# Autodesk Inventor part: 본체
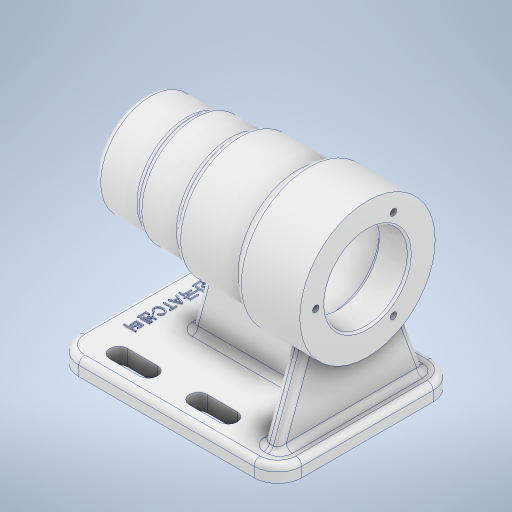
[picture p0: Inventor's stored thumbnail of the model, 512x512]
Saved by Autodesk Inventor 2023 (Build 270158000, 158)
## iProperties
Created: 2022-07
Part Number: 본체
Material: 알루미늄 6061
Document SubType Name: Modeling
Designer: owner
Density: 2.7 g/cm^3
Appearance: 알루미늄 - 평지
Mass: 695.124 g
Surface Area: 704.983 cm^2
Volume: 257.453 cm^3
Author: owner
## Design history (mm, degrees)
sketch "스케치1"
  geometry: L1 (44, -45)-(-44, -45); L2 (-56, -33)-(-56, 33); L3 (-44, 45)-(44, 45); L4 (56, 33)-(56, -33); L5 (56, -45)-(-56, 45); L6 (-56, -45)-(56, 45); A1 r 12 centre (44, -33) between (44, -45) and (56, -33); A2 r 12 centre (44, 33) between (56, 33) and (44, 45); A3 r 12 centre (-44, 33) between (-44, 45) and (-56, 33); A4 r 12 centre (-44, -33) between (-56, -33) and (-44, -45); 1 further point
  constraints: 12 end point, 8 point on circle, 8 point on line, 8 tangent, 4 centre point, 3 equal radius, 2 midpoint, 2 parallel, 1 horizontal, 1 perpendicular
  dimensions: "d0" = 112 distance of L5.end L6.end; "d1" = 90 distance of L6.start L5.end; "d2" = 12 radius of A1
extrude "돌출1" new body sketch "스케치1" distance "d3" = 8; taper "d4" = 0 deg
sketch "스케치2"
  geometry: L1 (-36, 33)-(-21, 33); L2 (-36, 28.5)-(-21, 28.5); L3 (-21, 37.5)-(-36, 37.5); L4 (4, 33)-(19, 33); L5 (4, 28.5)-(19, 28.5); L6 (19, 37.5)-(4, 37.5); L7 (56, -33)-(56, 33) reference; L8 (-56, 33)-(-56, -33) reference; L9 (-56, 33)-(-56, -33) reference; L10 (-56, 0)-(56, 0); L11 (-21, -37.5)-(-36, -37.5); L12 (-36, -28.5)-(-21, -28.5); L13 (19, -37.5)-(4, -37.5); L14 (4, -28.5)-(19, -28.5); A1 r 4.5 centre (-36, 33) between (-36, 37.5) and (-36, 28.5); A2 r 4.5 centre (-21, 33) between (-21, 28.5) and (-21, 37.5); A3 r 4.5 centre (4, 33) between (4, 37.5) and (4, 28.5); A4 r 4.5 centre (19, 33) between (19, 28.5) and (19, 37.5); A5 r 4.5 centre (-21, -33) between (-21, -37.5) and (-21, -28.5); A6 r 4.5 centre (-36, -33) between (-36, -28.5) and (-36, -37.5); A7 r 4.5 centre (4, -33) between (4, -28.5) and (4, -37.5); A8 r 4.5 centre (19, -33) between (19, -37.5) and (19, -28.5); 3 further points
  constraints: 26 end point, 16 point on circle, 12 symmetric about line, 8 centre point, 8 tangent, 4 midpoint, 2 horizontal, 2 parallel, 4 other
  dimensions: "d5" = 15 distance of L1.start L1.end; "d6" = 9 diameter of A2; "d7" = 15 distance of L4.start L4.end; "d8" = 9 diameter of A4; "d10" = 33 vertical distance of point (0, 0) point (-28.5, 33); "d11" = 33 vertical distance of point (0, 0) point (11.5, 33); "d12" = 25 distance of L4.start L1.end; "d13" = 20 distance from line of L8 L1.start
extrude "돌출2" cut sketch "스케치2" extent not by distance; stored distance "d14" = 0; taper "d15" = 0 deg
sketch "스케치3"
  geometry: L1 (-56, 70)-(56, 70); L2 (-44, 0)-(44, 0) reference; L3 (56, 70)-(56, 104); L4 (56, 104)-(24, 104); L5 (24, 104)-(24, 100); L6 (24, 100)-(-10, 100); L7 (-10, 100)-(-10, 97); L8 (-10, 97)-(-32, 97); L9 (-32, 97)-(-32, 95); L10 (-32, 95)-(-56, 95); L11 (-56, 95)-(-56, 70); L12 (56, 91)-(41, 91); L13 (41, 91)-(41, 91); L14 (38, 94)-(-10, 94); L15 (-13, 91)-(-13, 91); L16 (-13, 91)-(-24.7, 91); L17 (-25, 90.7)-(-25, 87.5); L18 (-25, 87.5)-(-42.7, 87.5); L19 (-43, 87.2)-(-43, 86); L20 (-43, 86)-(-46.7, 86); L21 (-47, 85.7)-(-47, 80.5); L22 (-47, 80.5)-(-47, 80.5); L23 (-50, 77.5)-(-50, 70); A1 r 3 centre (-47, 77.5) between (-47, 80.5) and (-50, 77.5); A2 r 0.3 centre (-46.7, 85.7) between (-46.7, 86) and (-47, 85.7); A3 r 0.3 centre (-42.7, 87.2) between (-42.7, 87.5) and (-43, 87.2); A4 r 3 centre (-10, 91) between (-10, 94) and (-13, 91); A5 r 3 centre (38, 91) between (41, 91) and (38, 94); A6 r 0.3 centre (-24.7, 90.7) between (-24.7, 91) and (-25, 90.7); 6 further points
  constraints: 44 end point, 18 perpendicular, 12 point on circle, 12 tangent, 6 centre point, 2 equal radius, 2 horizontal, 2 point on line, 2 vertical, 2 vertical alignment
  dimensions: "d16" = 70 distance between parallel lines of L2 L1; "d17" = 80 distance between parallel lines of L11 L5; "d18" = 46 distance between parallel lines of L11 L7; "d19" = 24 distance between parallel lines of L11 L9; "d20" = 68 diameter of L4 L1; "d21" = 60 diameter of L6 L1; "d22" = 54 diameter of L8 L1; "d23" = 50 diameter of L10 L1; "d24" = 21 diameter of L22 L1; "d25" = 32 diameter of L20 L1; "d26" = 35 diameter of L18 L1; "d27" = 42 diameter of L16 L1; "d28" = 48 diameter of L14 L1; "d29" = 42 diameter of L12 L1; "d30" = 18 distance between parallel lines of L17 L19; "d31" = 12 distance between parallel lines of L15 L17; "d32" = 54 distance between parallel lines of L13 L15; "d33" = 15 distance between parallel lines of L3 L13; "d35" = 4 distance between parallel lines of L19 L21; "d36" = 3 distance between parallel lines of L21 L23; "d37" = 3 radius of A1; "d38" = 0.3 radius of A2; "d39" = 3 radius of A4; "d40" = 0.3 radius of A6
revolve "회전1" sketch "스케치3" stored, may be unused: angle "d41" = 90 deg
fillet "모깎기1" dims "d42" = 1
fillet "모깎기2" dims "d43" = 3
fillet "모깎기3" dims "d44" = 3
sketch "스케치4" dims "d52" = 52
  geometry: C1 r 34 at (0, 0) reference; C2 r 10.5 at (0, 0) reference; C3 r 7.5 at (0, 0) reference; 4 further points
  constraints: 3 horizontal alignment, 1 coincident, 2 other
hole "구멍1" sketch "스케치4" at (-26, 0) diameter "d45" = 3.242; stored, may be unused: countersink angle "d49" = 90 deg, drill point angle "d51" = 0 deg; dims "d46" = 8, "d47" = 4, "d48" = 2, "d50" = 11.8
node "작업 평면1"
sketch "스케치6"
  geometry: L1 (9.591, 45.342)-(-4, 8); L2 (0, 8)-(66, 8) reference; L3 (-12, 0)-(-12, 8) reference; L4 (33, 0)-(33, 70); L5 (56.409, 45.342)-(70, 8); L6 (61.5, 8)-(70.5, 8) reference; L7 (70.5, 8)-(-4, 8); 2 further points
  constraints: 8 end point, 2 symmetric about line, 1 collinear, 1 point on line, 1 vertical, 2 other
  dimensions: "d66" = 110 deg angle of L2 L1; "d67" = 8 distance from line of L3 L1.end
extrude "돌출4" join sketch "스케치6" distance "d68" = 8; taper "d69" = 0 deg
sketch "스케치7"
  geometry: L1 (-30.356, 43)-(-13, 43) reference; L2 (-19.622, 43)-(-29, 8); L3 (44, 8)-(-44, 8) reference; L4 (56, 0)-(56, 8) reference; L5 (48, 124.8)-(48, -20.8) reference; 1 further point
  constraints: 2 end point, 2 point on line
  dimensions: "d70" = 105 deg angle of L3 L2; "d72" = 77 distance from line of L5 L2.end
feature "리브1" sketch "스케치7" dims "d73" = 1, "d74" = 8, "d75" = 0, "d76" = 0, "d77" = 1, "d78" = 1
fillet "모깎기4" dims "d79" = 3
fillet "모깎기5" dims "d80" = 3
fillet "모깎기6" dims "d81" = 3
sketch "스케치8"
  geometry: L1 (-56, 33)-(-56, -33) reference; A1 r 4.5 centre (-36, 33) between (-36, 37.5) and (-36, 28.5) reference; 3 further points
  constraints: 1 point on circle, 1 other
  dimensions: "d82" = 12 distance from line of L1 point (-44, 0); "d83" = 33 vertical distance of point (-44, 0) point (-40.5, 33)
feature "엠보싱1" sketch "스케치8" dims "d0" = 112, "d1" = 90, "d2" = 12, "d84" = 0.5, "d85" = 0
node "솔리드1"
pattern_circular "원형 패턴1" dims angle "d56" = 360 deg
feature "A9D066F2-1C7D-4E18-AEED-F7BC21143FA4" dims "d45" = 3.242, "d46" = 8, "d47" = 4, "d48" = 2, "d49" = 90 deg, "d50" = 11.8, "d51" = 0
other parameters: "d65" = -8
